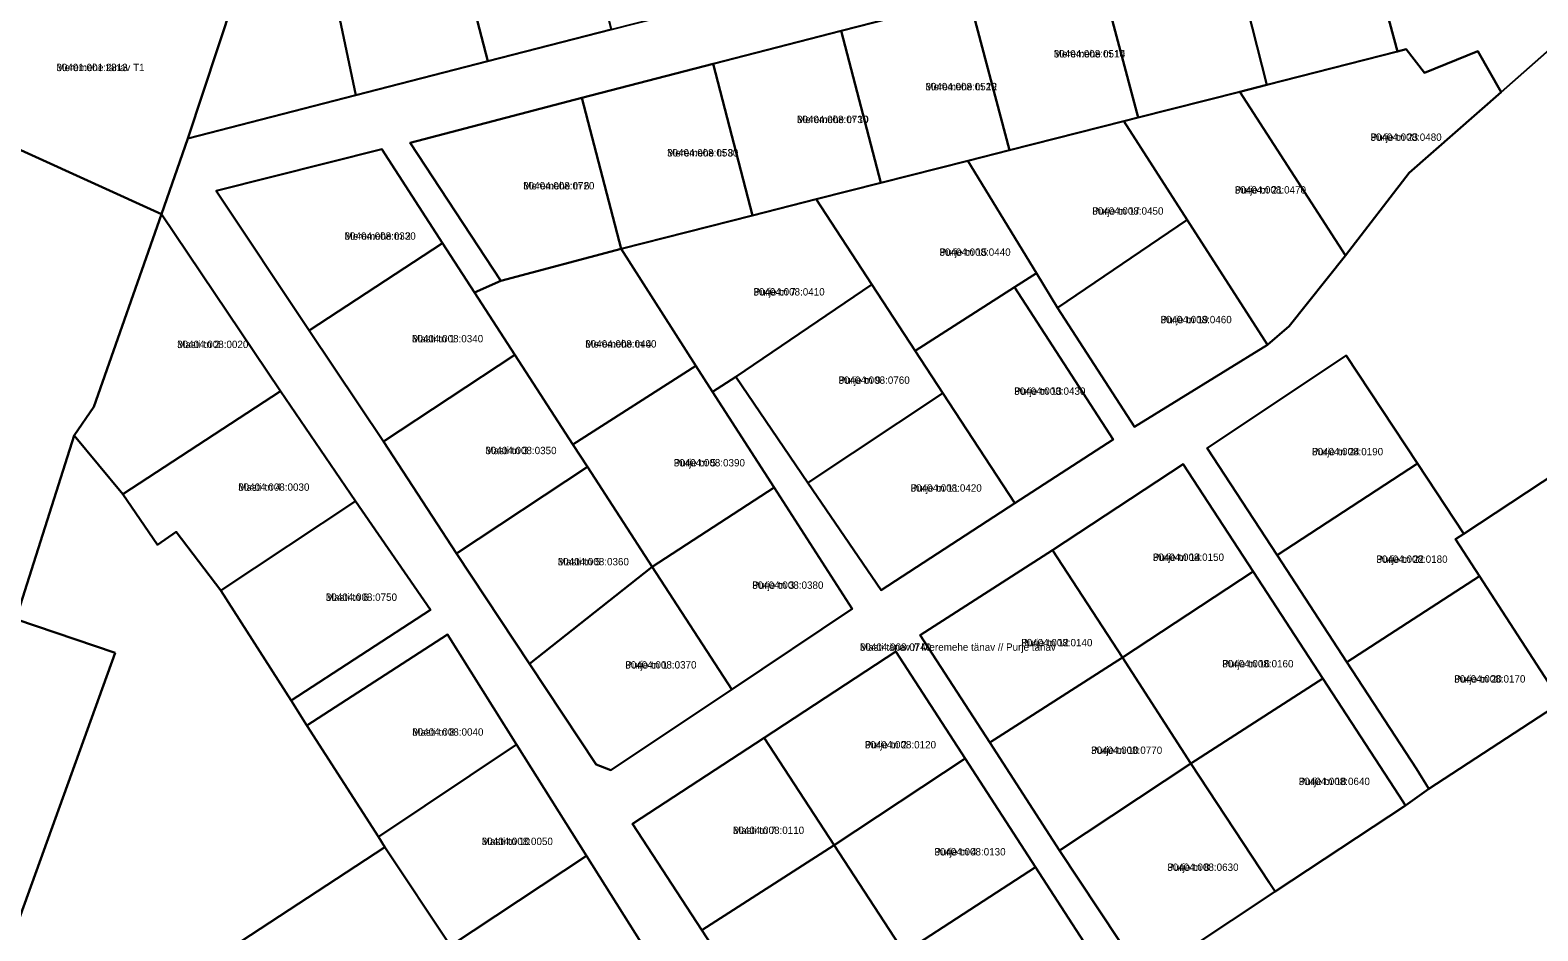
# Model space of a CAD drawing. Extents: x 542681 to 554572, y 6566489 to 6580482.
# Drawn here: x 543956.1 to 544263.2, y 6576713.2 to 6576896.6 of the extents above; entities that cross this region are included whole.
import ezdxf

# ---------------------------------------------------------------- set-up
doc = ezdxf.new("R2010")
doc.units = 0
for name, color, linetype in [('L_AADRESS', 7, 'Continuous'), ('PIIR', 7, 'Continuous'), ('TUNNUS', 7, 'Continuous')]:
    doc.layers.add(name, color=color, linetype=linetype)

msp = doc.modelspace()

# ---------------------------------------------------------------- linework, layer by layer
at = {"layer": 'PIIR'}
for points in [[(544083.14, 6576706.63), (544069.43, 6576728.43), (544055.16, 6576751.13), (544041.07, 6576773.52), (544012.45, 6576754.96), (544009.2, 6576760.05), (544037.62, 6576778.58), (544022.31, 6576800.71), (544007.03, 6576823.11), (543982.8, 6576859.17), (543988.16, 6576874.59), (544022.38, 6576883.4), (544049.33, 6576890.31), (544074.45, 6576896.76), (544099.65, 6576903.25), (544125.05, 6576909.8), (544150.03, 6576916.24), (544175.24, 6576922.74), (544200.45, 6576929.24), (544225.66, 6576935.73), (544252.75, 6576942.7), (544257.68, 6576935.15), (544271.85, 6576913.23)], [(544183.03, 6576703.47), (544209.73, 6576721.14), (544236.26, 6576738.69), (544241.04, 6576742.08), (544267.97, 6576759.66), (544288.75, 6576773.4), (544309.62, 6576787.21), (544330.16, 6576800.8), (544331.93, 6576800.8), (544345.26, 6576800.49), (544351.31, 6576803.07), (544376.64, 6576820.65), (544374.32, 6576824.14), (544376.61, 6576825.66), (544417.35, 6576852.57), (544427.47, 6576859.62), (544454.09, 6576876.45), (544475.75, 6576890.64), (544479.2, 6576885.76), (544480.66, 6576886.66), (544482.53, 6576887.2), (544488.38, 6576890.18), (544515.24, 6576933.3), (544528.21, 6576893.68)], [(544147.38, 6576903.24), (544121.31, 6576896.51), (544095.22, 6576889.78), (544068.43, 6576882.82), (544033.45, 6576873.71), (544051.98, 6576845.56), (544046.61, 6576843.16), (544040.09, 6576853.23), (544027.67, 6576872.41), (543993.94, 6576863.9), (544012.92, 6576835.46), (544028.02, 6576812.84), (544042.89, 6576790.01), (544057.77, 6576767.54), (544071.35, 6576747.04), (544074.38, 6576745.89), (544098.99, 6576762.33), (544123.55, 6576778.72), (544107.63, 6576803.44), (544095.07, 6576822.97), (544099.8, 6576825.98), (544114.51, 6576804.4), (544129.42, 6576782.55), (544156.68, 6576800.25), (544176.71, 6576813.26), (544156.62, 6576844.28), (544161.06, 6576847.13), (544165.38, 6576840.04), (544181.06, 6576815.85), (544208.11, 6576832.55), (544212.57, 6576836.36), (544224.06, 6576850.76), (544237.03, 6576867.54), (544255.76, 6576884.03), (544267.28, 6576894.17)], [(544267.31, 6576806.67), (544248.12, 6576794.02), (544238.68, 6576808.38), (544224.19, 6576830.39), (544195.85, 6576811.48), (544210.09, 6576789.67), (544224.33, 6576767.86), (544238.48, 6576746.17), (544241.04, 6576742.08), (544236.26, 6576738.69), (544234.91, 6576740.77), (544219.41, 6576764.56), (544205.19, 6576786.37), (544190.96, 6576808.19), (544164.35, 6576790.7), (544137.37, 6576773.36), (544151.56, 6576751.55), (544165.77, 6576729.54), (544181.93, 6576705.13)], [(544176.69, 6576701.67), (544160.86, 6576726.12), (544146.56, 6576748.25), (544132.45, 6576770.05), (544105.59, 6576752.49), (544078.77, 6576734.94), (544092.9, 6576713.29), (544107.24, 6576691.31)]]:
    msp.add_lwpolyline(points, dxfattribs=at)
for points in [[(544040.24, 6576925.11), (544059.77, 6576930.04), (544065.46, 6576931.54), (544074.45, 6576896.76), (544049.33, 6576890.31)], [(544236.42, 6576892.73), (544234.62, 6576892.27), (544226.19, 6576923.47), (544248.56, 6576929.2), (544267.52, 6576899.03), (544267.28, 6576894.17), (544255.76, 6576884.03), (544251.02, 6576892.37), (544240.1, 6576887.96)], [(544014.9, 6576919.26), (544037.14, 6576924.33), (544040.24, 6576925.11), (544049.33, 6576890.31), (544022.38, 6576883.4)], [(544200.03, 6576916.78), (544226.19, 6576923.47), (544234.62, 6576892.27), (544208.01, 6576885.48)], [(543929.19, 6576883.52), (543932.34, 6576899.7), (543945.88, 6576902.92), (543991.03, 6576913.55), (543992.29, 6576917.41), (544000.54, 6576911.95), (543988.16, 6576874.59), (543982.8, 6576859.17)], [(544000.54, 6576911.95), (544004.39, 6576916.85), (544014.9, 6576919.26), (544022.38, 6576883.4), (543988.16, 6576874.59)], [(544173.51, 6576909.99), (544200.03, 6576916.78), (544208.01, 6576885.48), (544202.49, 6576884.08), (544181.8, 6576878.81)], [(544147.38, 6576903.24), (544173.51, 6576909.99), (544181.8, 6576878.81), (544178.89, 6576878.07), (544155.59, 6576872.18)], [(544121.31, 6576896.51), (544147.38, 6576903.24), (544155.59, 6576872.18), (544147.11, 6576870.03), (544129.37, 6576865.54)], [(544095.22, 6576889.78), (544121.31, 6576896.51), (544129.37, 6576865.54), (544116.16, 6576862.19), (544103.2, 6576858.91)], [(544068.43, 6576882.82), (544095.22, 6576889.78), (544103.2, 6576858.91), (544076.48, 6576852.09)], [(544202.49, 6576884.08), (544208.01, 6576885.48), (544234.62, 6576892.27), (544236.42, 6576892.73), (544240.1, 6576887.96), (544251.02, 6576892.37), (544255.76, 6576884.03), (544237.03, 6576867.54), (544224.06, 6576850.76)], [(544178.89, 6576878.07), (544181.8, 6576878.81), (544202.49, 6576884.08), (544224.06, 6576850.76), (544212.57, 6576836.36), (544208.11, 6576832.55), (544191.77, 6576858)], [(543923.5, 6576859.84), (543929.19, 6576883.52), (543982.8, 6576859.17), (543969.05, 6576819.92), (543964.99, 6576814.08), (543953.11, 6576776.64), (543898.38, 6576795.22), (543918.95, 6576845.61)], [(544033.45, 6576873.71), (544068.43, 6576882.82), (544076.48, 6576852.09), (544051.98, 6576845.56)], [(544161.06, 6576847.13), (544147.11, 6576870.03), (544155.59, 6576872.18), (544178.89, 6576878.07), (544191.77, 6576858), (544165.38, 6576840.04)], [(544027.67, 6576872.41), (544040.09, 6576853.23), (544012.92, 6576835.46), (543993.94, 6576863.9)], [(544127.55, 6576844.79), (544116.16, 6576862.19), (544129.37, 6576865.54), (544147.11, 6576870.03), (544161.06, 6576847.13), (544156.62, 6576844.28), (544136.37, 6576831.3)], [(544095.07, 6576822.97), (544091.69, 6576828.24), (544076.48, 6576852.09), (544103.2, 6576858.91), (544116.16, 6576862.19), (544127.55, 6576844.79), (544099.8, 6576825.98)], [(543964.99, 6576814.08), (543969.05, 6576819.92), (543982.8, 6576859.17), (544007.03, 6576823.11), (543974.95, 6576802.11)], [(544165.38, 6576840.04), (544191.77, 6576858), (544208.11, 6576832.55), (544181.06, 6576815.85)], [(544012.92, 6576835.46), (544040.09, 6576853.23), (544046.61, 6576843.16), (544054.8, 6576830.51), (544028.02, 6576812.84)], [(544054.8, 6576830.51), (544046.61, 6576843.16), (544051.98, 6576845.56), (544076.48, 6576852.09), (544091.69, 6576828.24), (544066.64, 6576812.21)], [(544099.8, 6576825.98), (544127.55, 6576844.79), (544136.37, 6576831.3), (544142.01, 6576822.68), (544114.51, 6576804.4)], [(544142.01, 6576822.68), (544136.37, 6576831.3), (544156.62, 6576844.28), (544176.71, 6576813.26), (544156.68, 6576800.25)], [(544028.02, 6576812.84), (544054.8, 6576830.51), (544066.64, 6576812.21), (544069.57, 6576807.68), (544042.89, 6576790.01)], [(544195.85, 6576811.48), (544224.19, 6576830.39), (544238.68, 6576808.38), (544210.09, 6576789.67)], [(544069.57, 6576807.68), (544066.64, 6576812.21), (544091.69, 6576828.24), (544095.07, 6576822.97), (544107.63, 6576803.44), (544082.8, 6576787.29)], [(543985.82, 6576794.41), (543981.99, 6576791.82), (543974.95, 6576802.11), (544007.03, 6576823.11), (544022.31, 6576800.71), (543994.87, 6576782.5)], [(544114.51, 6576804.4), (544142.01, 6576822.68), (544156.68, 6576800.25), (544129.42, 6576782.55)], [(543973.39, 6576769.78), (543953.11, 6576776.64), (543964.99, 6576814.08), (543974.95, 6576802.11), (543981.99, 6576791.82), (543985.82, 6576794.41), (543994.87, 6576782.5), (544009.2, 6576760.05), (544012.45, 6576754.96), (544027, 6576732.31), (544028.33, 6576730.2), (543995.02, 6576708.39), (543961.37, 6576686.48), (543957.54, 6576684.34), (543954.8, 6576682.81), (543948.88, 6576679.53), (543821.12, 6576608.68), (543839.75, 6576654.18), (543848.49, 6576677.12), (543870.89, 6576733.03), (543949.95, 6576704.85)], [(544042.89, 6576790.01), (544069.57, 6576807.68), (544082.8, 6576787.29), (544057.77, 6576767.54)], [(544164.35, 6576790.7), (544190.96, 6576808.19), (544205.19, 6576786.37), (544178.6, 6576768.85)], [(544238.68, 6576808.38), (544248.12, 6576794.02), (544246.45, 6576792.92), (544251.34, 6576785.38), (544224.33, 6576767.86), (544210.09, 6576789.67)], [(544265.31, 6576763.78), (544251.34, 6576785.38), (544246.45, 6576792.92), (544248.12, 6576794.02), (544267.31, 6576806.67), (544286.81, 6576776.36), (544288.75, 6576773.4), (544267.97, 6576759.66)], [(544037.62, 6576778.58), (544009.2, 6576760.05), (543994.87, 6576782.5), (544022.31, 6576800.71)], [(544082.8, 6576787.29), (544107.63, 6576803.44), (544123.55, 6576778.72), (544098.99, 6576762.33)], [(543973.39, 6576769.78), (543949.95, 6576704.85), (543870.89, 6576733.03), (543898.38, 6576795.22), (543953.11, 6576776.64)], [(544178.6, 6576768.85), (544151.56, 6576751.55), (544137.37, 6576773.36), (544164.35, 6576790.7)], [(544082.8, 6576787.29), (544098.99, 6576762.33), (544074.38, 6576745.89), (544071.35, 6576747.04), (544057.77, 6576767.54)], [(544178.6, 6576768.85), (544205.19, 6576786.37), (544219.41, 6576764.56), (544192.54, 6576747.26)], [(544238.48, 6576746.17), (544224.33, 6576767.86), (544251.34, 6576785.38), (544265.31, 6576763.78), (544267.97, 6576759.66), (544241.04, 6576742.08)], [(544012.45, 6576754.96), (544041.07, 6576773.52), (544055.16, 6576751.13), (544027, 6576732.31)], [(544105.59, 6576752.49), (544132.45, 6576770.05), (544146.56, 6576748.25), (544119.88, 6576730.59)], [(544178.6, 6576768.85), (544192.54, 6576747.26), (544165.77, 6576729.54), (544151.56, 6576751.55)], [(544208.5, 6576723.01), (544192.54, 6576747.26), (544219.41, 6576764.56), (544234.91, 6576740.77), (544236.26, 6576738.69), (544209.73, 6576721.14)], [(544078.77, 6576734.94), (544105.59, 6576752.49), (544119.88, 6576730.59), (544092.9, 6576713.29)], [(544028.33, 6576730.2), (544027, 6576732.31), (544055.16, 6576751.13), (544069.43, 6576728.43), (544041.69, 6576710.13)], [(544119.88, 6576730.59), (544146.56, 6576748.25), (544160.86, 6576726.12), (544134.12, 6576708.76)], [(544181.93, 6576705.13), (544165.77, 6576729.54), (544192.54, 6576747.26), (544208.5, 6576723.01), (544209.73, 6576721.14), (544183.03, 6576703.47)], [(544009.01, 6576687.6), (543995.02, 6576708.39), (544028.33, 6576730.2), (544041.69, 6576710.13), (544042.25, 6576709.3), (544012.53, 6576689.9)], [(544134.12, 6576708.76), (544107.24, 6576691.31), (544092.9, 6576713.29), (544119.88, 6576730.59)], [(544042.25, 6576709.3), (544041.69, 6576710.13), (544069.43, 6576728.43), (544083.14, 6576706.63), (544055.95, 6576688.87)], [(544150.19, 6576684.14), (544148.44, 6576686.82), (544134.12, 6576708.76), (544160.86, 6576726.12), (544176.69, 6576701.67), (544177.78, 6576699.99), (544151.28, 6576682.47)]]:
    msp.add_lwpolyline(points, close=True, dxfattribs=at)

# ---------------------------------------------------------------- texts
at = {"layer": 'L_AADRESS'}
for s, p in [('Meremehe tänav T1', (543961.41, 6576888.29)), ('Meremehe tn 14', (544164.59, 6576891.07)), ('Meremehe tn 12', (544138.45, 6576884.39)), ('Meremehe tn 10', (544112.29, 6576877.7)), ('Purje tn 23', (544229.12, 6576874.09)), ('Meremehe tn 8', (544085.82, 6576870.9)), ('Meremehe tn 6', (544056.51, 6576864.19)), ('Purje tn 21', (544201.48, 6576863.35)), ('Purje tn 17', (544172.44, 6576859.05)), ('Meremehe tn 2', (544020.11, 6576853.94)), ('Purje tn 15', (544141.31, 6576850.67)), ('Purje tn 7', (544103.42, 6576842.58)), ('Purje tn 19', (544186.35, 6576836.93)), ('Masti tn 1', (544033.85, 6576833.04)), ('Masti tn 2', (543986.01, 6576831.87)), ('Meremehe tn 4', (544069.15, 6576831.98)), ('Purje tn 9', (544120.75, 6576824.59)), ('Purje tn 13', (544156.54, 6576822.35)), ('Masti tn 3', (544048.8, 6576810.26)), ('Purje tn 24', (544217.2, 6576810.03)), ('Purje tn 5', (544087.18, 6576807.76)), ('Masti tn 4', (543998.45, 6576802.8)), ('Purje tn 11', (544135.43, 6576802.62)), ('Masti tn 5', (544063.54, 6576787.61)), ('Purje tn 14', (544184.78, 6576788.52)), ('Purje tn 22', (544230.33, 6576788.12)), ('Purje tn 3', (544103.17, 6576782.83)), ('Masti tn 6', (544016.3, 6576780.38)), ('Masti tänav // Meremehe tänav // Purje tänav', (544125.11, 6576770.21)), ('Purje tn 12', (544157.97, 6576771.12)), ('Purje tn 1', (544077.31, 6576766.59)), ('Purje tn 16', (544198.93, 6576766.82)), ('Purje tn 20', (544246.18, 6576763.73)), ('Masti tn 8', (544033.9, 6576752.91)), ('Purje tn 2', (544126.11, 6576750.32)), ('Purje tn 10', (544172.19, 6576749.2)), ('Purje tn 18', (544214.5, 6576742.85)), ('Masti tn 7', (544099.24, 6576732.89)), ('Masti tn 10', (544048.05, 6576730.63)), ('Purje tn 4', (544140.28, 6576728.51)), ('Purje tn 8', (544187.74, 6576725.37))]:
    msp.add_text(s, height=1.5, dxfattribs=at).set_placement(p)
at = {"layer": 'TUNNUS'}
for s, p in [('30401:001:2813', (543961.41, 6576888.29)), ('30404:008:0510', (544164.59, 6576891.07)), ('30404:008:0520', (544138.45, 6576884.39)), ('30404:008:0730', (544112.29, 6576877.7)), ('30404:008:0480', (544229.12, 6576874.09)), ('30404:008:0530', (544085.82, 6576870.9)), ('30404:008:0720', (544056.51, 6576864.19)), ('30404:008:0470', (544201.48, 6576863.35)), ('30404:008:0450', (544172.44, 6576859.05)), ('30404:008:0330', (544020.11, 6576853.94)), ('30404:008:0440', (544141.31, 6576850.67)), ('30404:008:0410', (544103.42, 6576842.58)), ('30404:008:0460', (544186.35, 6576836.93)), ('30404:008:0340', (544033.85, 6576833.04)), ('30404:008:0020', (543986.01, 6576831.87)), ('30404:008:0400', (544069.15, 6576831.98)), ('30404:008:0760', (544120.75, 6576824.59)), ('30404:008:0430', (544156.54, 6576822.35)), ('30404:008:0350', (544048.8, 6576810.26)), ('30404:008:0190', (544217.2, 6576810.03)), ('30404:008:0390', (544087.18, 6576807.76)), ('30404:008:0030', (543998.45, 6576802.8)), ('30404:008:0420', (544135.43, 6576802.62)), ('30404:008:0360', (544063.54, 6576787.61)), ('30404:008:0150', (544184.78, 6576788.52)), ('30404:008:0180', (544230.33, 6576788.12)), ('30404:008:0380', (544103.17, 6576782.83)), ('30404:008:0750', (544016.3, 6576780.38)), ('30404:008:0740', (544125.11, 6576770.21)), ('30404:008:0140', (544157.97, 6576771.12)), ('30404:008:0370', (544077.31, 6576766.59)), ('30404:008:0160', (544198.93, 6576766.82)), ('30404:008:0170', (544246.18, 6576763.73)), ('30404:008:0040', (544033.9, 6576752.91)), ('30404:008:0120', (544126.11, 6576750.32)), ('30404:008:0770', (544172.19, 6576749.2)), ('30404:008:0640', (544214.5, 6576742.85)), ('30404:008:0110', (544099.24, 6576732.89)), ('30404:008:0050', (544048.05, 6576730.63)), ('30404:008:0130', (544140.28, 6576728.51)), ('30404:008:0630', (544187.74, 6576725.37))]:
    msp.add_text(s, height=1.5, dxfattribs=at).set_placement(p)

doc.saveas('drawing.dxf')
